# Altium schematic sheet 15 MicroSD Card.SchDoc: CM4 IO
size 297 x 209 mm; Page Create Date: March  8, 1995; Page Number: 15; Page Size: A4; Comment: radxa_1010; Page Count: 19; RevCode: V1.10; Doc: 15 MicroSD Card; DsnPath: D:\WMS\黄工\[RC126]CM4_IO_V1.10\[RC126]_V1.10\CM4 IO_V1.10.DSN; SchematicName: CM4 IO V1.10; PageName: 15 MicroSD Card; PageSize: A4; TopSchematic: True
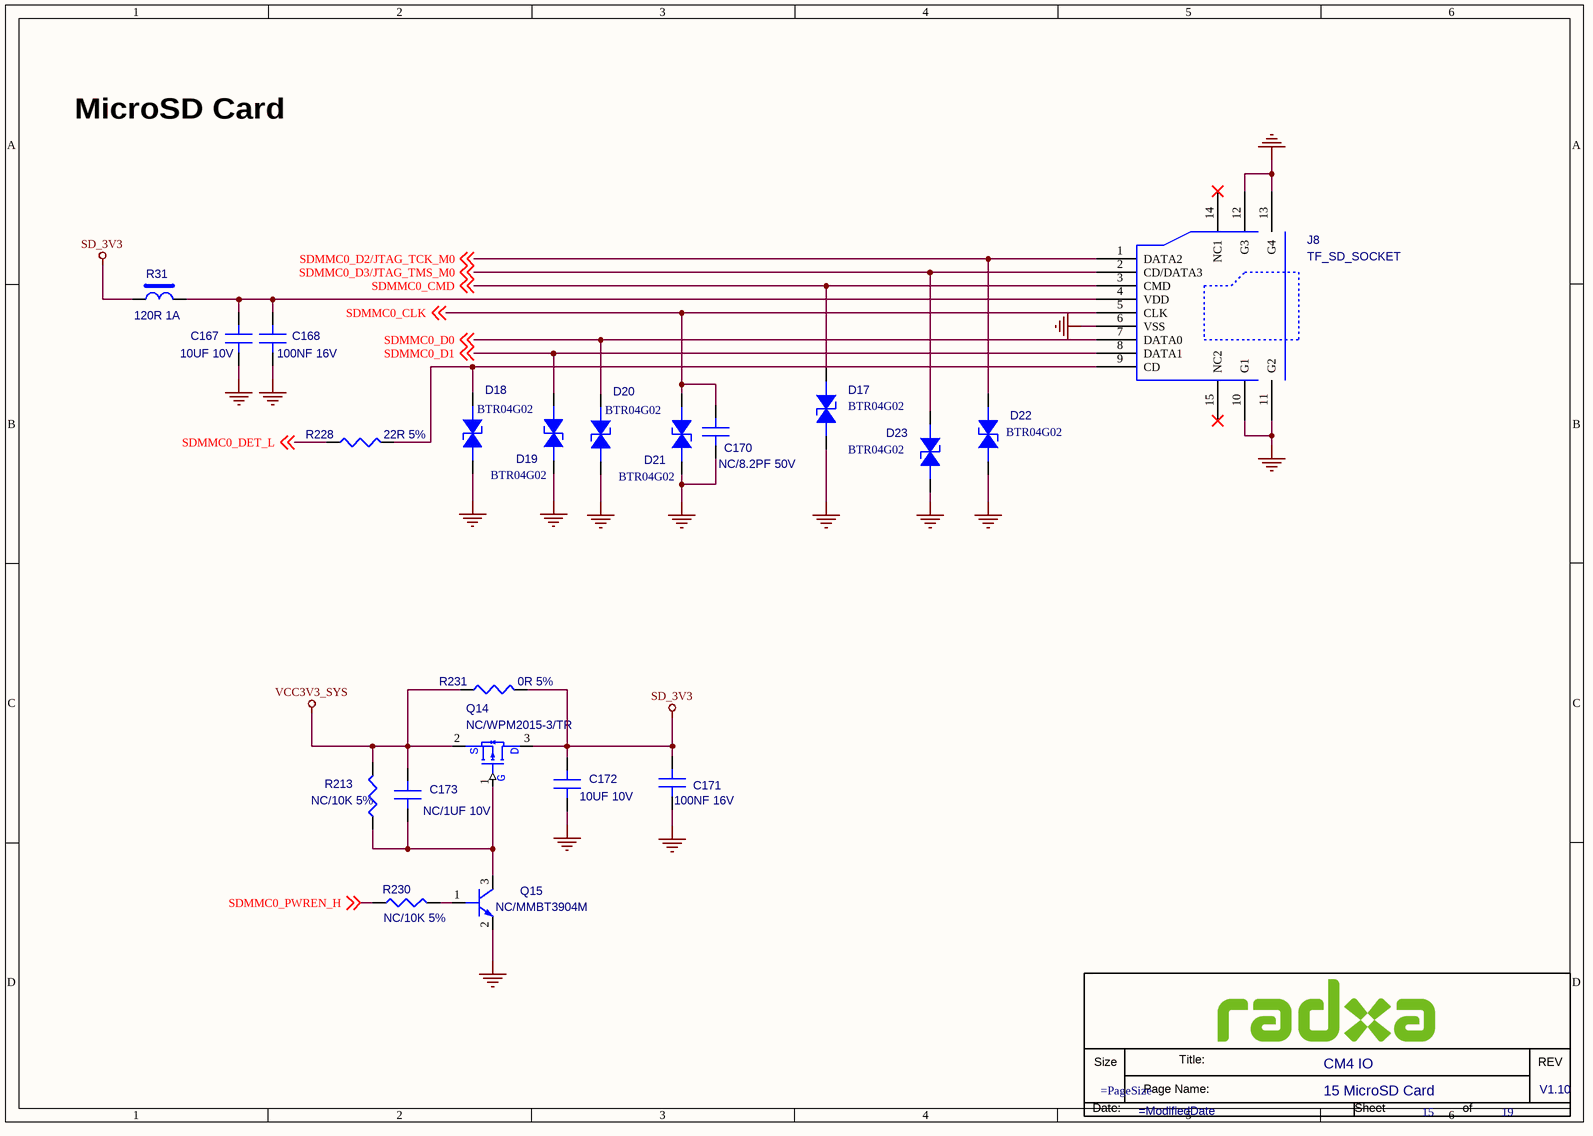
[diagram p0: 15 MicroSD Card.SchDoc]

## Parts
*  Doc: 15 MicroSD Card  RevCode: V1.10  Title: CM4 IO  Page Number: 15  Page Count: 19  (hidden comment: radxa_1010)  (graphical)
C167  10UF 10V  [C0603]
C168  100NF 16V  [C0201]
C170  NC/8.2PF 50V  [C0201]
C171  100NF 16V  [C0201]
C172  10UF 10V  [C0603]
C173  NC/1UF 10V  [C0201]
D17  BTR04G02  [DFN1006-2L]
D18  BTR04G02  [DFN1006-2L]
D19  BTR04G02  [DFN1006-2L]
D20  BTR04G02  [DFN1006-2L]
D21  BTR04G02  [DFN1006-2L]
D22  BTR04G02  [DFN1006-2L]
D23  BTR04G02  [DFN1006-2L]
J8  TF_SD_SOCKET  [SD_SM9_1D1_15D75]
Q14  NC/WPM2015-3/TR  [SOT_23]
Q15  NC/MMBT3904M  [SOT_723]
R31  120R 1A  [FB0201]
R213  NC/10K 5%  [R0402]
R228  22R 5%  [R0402]
R230  NC/10K 5%  [R0402]
R231  0R 5%  [R0402]

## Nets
GND: C167.2(B) C168.2(B) C170.2(B) C171.2(B) C172.2(B) D17.1(ANODE) D18.1(ANODE) D19.1(ANODE) D20.1(ANODE) D21.1(ANODE) D22.1(ANODE) D23.1(ANODE) J8.6(VSS) J8.10(G1) J8.11(G2) J8.12(G3) J8.13(G4) Q15.2(EMITTER)
SD_3V3: C171.1(A) C172.1(A) Q14.3(D) R31.1 R231.2
VCC3V3_SYS: C173.1(A) Q14.2(S) R213.2 R231.1
SDMMC0_CLK: C170.1(A) D21.2(CATHODE) J8.5(CLK) ; off-sheet SDMMC0_CLK
SDMMC0_CMD: D17.2(CATHODE) J8.3(CMD) ; off-sheet SDMMC0_CMD
SDMMC0_D0: D20.2(CATHODE) J8.7(DATA0) ; off-sheet SDMMC0_D0
SDMMC0_D1: D19.2(CATHODE) J8.8(DATA1) ; off-sheet SDMMC0_D1
SDMMC0_D2/JTAG_TCK_M0: D22.2(CATHODE) J8.1(DATA2) ; off-sheet SDMMC0_D2/JTAG_TCK_M0
SDMMC0_D3/JTAG_TMS_M0: D23.2(CATHODE) J8.2(CD/DATA3) ; off-sheet SDMMC0_D3/JTAG_TMS_M0
SDMMC0_DET_L: R228.1 ; off-sheet SDMMC0_DET_L
SDMMC0_PWREN_H: R230.1 ; off-sheet SDMMC0_PWREN_H
NetC167_1: C167.1(A) C168.1(A) J8.4(VDD) R31.2
NetC173_2: C173.2(B) Q14.1(G) Q15.3(COLLECTOR) R213.1
NetD18_2: D18.2(CATHODE) J8.9(CD) R228.2
NetQ15_1: Q15.1(BASE) R230.2

Not connected (* = marked no-connect by the designer): J8 14(NC1)* 15(NC2)*

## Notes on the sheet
- MicroSD Card

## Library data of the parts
C167 = C: SMD  0603  10UF  10V  X5R  ±10%  ROHS; PARTS: 1; Part Reference: C167; Part Number: A1C01.00270; OriginalSymbolOrigin: (0,30); PKG_TYPE: CAP2-100-250; LEVEL: STD; PINSWAP: (A,B)
C168 = C: SMD  0201  100NF  16V  X5R  ±20%  ROHS; PARTS: 1; Part Reference: C168; Part Number: A1C01.00099; OriginalSymbolOrigin: (0,30); PKG_TYPE: CAP2-100-250; LEVEL: STD; PINSWAP: (A,B); Preferred: 6715f349cd0bc5
C170 = C: SMD  0201  8.2PF  50V  NPO  ±5%  ROHS; PARTS: 1; Part Reference: C170; Part Number: A1C01.00147; OriginalSymbolOrigin: (0,30); PKG_TYPE: CAP2-100-250; LEVEL: STD; PINSWAP: (A,B)
C171 = C: SMD  0201  100NF  16V  X5R  ±20%  ROHS; PARTS: 1; Part Reference: C171; Part Number: A1C01.00099; OriginalSymbolOrigin: (0,30); PKG_TYPE: CAP2-100-250; LEVEL: STD; PINSWAP: (A,B); Preferred: 6715f349cd0bc5
C172 = C: SMD  0603  10UF  10V  X5R  ±20%  ROHS; PARTS: 1; Part Reference: C172; Part Number: A1C01.00075; OriginalSymbolOrigin: (0,30); PKG_TYPE: CAP2-100-250; LEVEL: STD; PINSWAP: (A,B)
C173 = C: SMD  0201  1UF  10V  X5R  ±20%  ROHS; PARTS: 1; Part Reference: C173; Part Number: A1C01.00081; OriginalSymbolOrigin: (0,30); PKG_TYPE: CAP2-100-250; LEVEL: STD; PINSWAP: (A,B)
D17 = ESD: SMD  编带  0402  BTR04G02  B-tron  ROHS; Part Reference: D17; Part Number: A1D02.00002; Parameter: ESD-台舟 ESD5341N-封装 esd0402; ID: DE-E0004; Temp Coeff: -50℃ ~ +125℃; PCB Footprint: ESD_D0402
D18 = ESD: SMD  编带  0402  BTR04G02  B-tron  ROHS; Part Reference: D18; Part Number: A1D02.00002; Parameter: ESD-台舟 ESD5341N-封装 esd0402; ID: DE-E0004; Temp Coeff: -50℃ ~ +125℃; PCB Footprint: ESD_D0402
D19 = ESD: SMD  编带  0402  BTR04G02  B-tron  ROHS; Part Reference: D19; Part Number: A1D02.00002; Parameter: ESD-台舟 ESD5341N-封装 esd0402; ID: DE-E0004; Temp Coeff: -50℃ ~ +125℃; PCB Footprint: ESD_D0402
D20 = ESD: SMD  编带  0402  BTR04G02  B-tron  ROHS; Part Reference: D20; Part Number: A1D02.00002; Parameter: ESD-台舟 ESD5341N-封装 esd0402; ID: DE-E0004; Temp Coeff: -50℃ ~ +125℃; PCB Footprint: ESD_D0402
D21 = ESD: SMD  编带  0402  BTR04G02  B-tron  ROHS; Part Reference: D21; Part Number: A1D02.00002; Parameter: ESD-台舟 ESD5341N-封装 esd0402; ID: DE-E0004; Temp Coeff: -50℃ ~ +125℃; PCB Footprint: ESD_D0402
D22 = ESD: SMD  编带  0402  BTR04G02  B-tron  ROHS; Part Reference: D22; Part Number: A1D02.00002; Parameter: ESD-台舟 ESD5341N-封装 esd0402; ID: DE-E0004; Temp Coeff: -50℃ ~ +125℃; PCB Footprint: ESD_D0402
D23 = ESD: SMD  编带  0402  BTR04G02  B-tron  ROHS; Part Reference: D23; Part Number: A1D02.00002; Parameter: ESD-台舟 ESD5341N-封装 esd0402; ID: DE-E0004; Temp Coeff: -50℃ ~ +125℃; PCB Footprint: ESD_D0402
J8 = TF_SD_SOCKET: SMD  XKTF-N02-N  14.7*14.8*H1.95mm  9PIN  不锈钢  星坤  ROHS; Part Reference: J8; Part Number: A1J09.00014; Preferred: 6715f349cd0bc5; Temp Coeff: -30℃ to +80℃
Q14 = MOSFET_PNP: SMD编带  SOT-23  WPM2015-3/TR  P沟道  ROHS; Part Reference: Q14; Part Number: A1D01.00019; Temp Coeff: -55℃ to ＋150℃
Q15 = NPN: SMD编带  SOT-723  MMBT3904M  NPN  ROHS; Part Reference: Q15; Manufacturer PN: S8050_SOT23; Manufacturer: 长电; Part Number: A1D01.00002; Pc: 0.3W; Vceo: 25V; Ic: 0.5A; Priority: A; RK PN: S8050; Temp Coeff: -55℃ to ＋150℃
R31 = BEAD: SMD  0201  FB120R  1A  MPZ0603S121HT000  ±25%  ROHS; Part Reference: R31; Part Number: A1L09.00033
R213 = R: SMD  0201  10K  1/20W  ±5%  ROHS; Part Reference: R213; Part Number: A1R01.00012; PCB Footprint: R0201; Temp Coeff: －55℃ ~ ＋125℃
R228 = R: SMD  0201  22R  1/20W  ±5%  ROHS; Part Reference: R228; Part Number: A1R01.00024; PCB Footprint: R0201; Temp Coeff: -55℃ to +125℃; Preferred: 6715f349cd0bc5
R230 = R: SMD  0201  10K  1/20W  ±5%  ROHS; Part Reference: R230; Part Number: A1R01.00012; PCB Footprint: R0201; Temp Coeff: －55℃ ~ ＋125℃
R231 = R: SMD  0201  0R  1/20W  ±5%  ROHS; Part Reference: R231; Part Number: A1R01.00027; PCB Footprint: R0201; Temp Coeff: -55℃ to +125℃; Preferred: 6715f349cd0bc5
